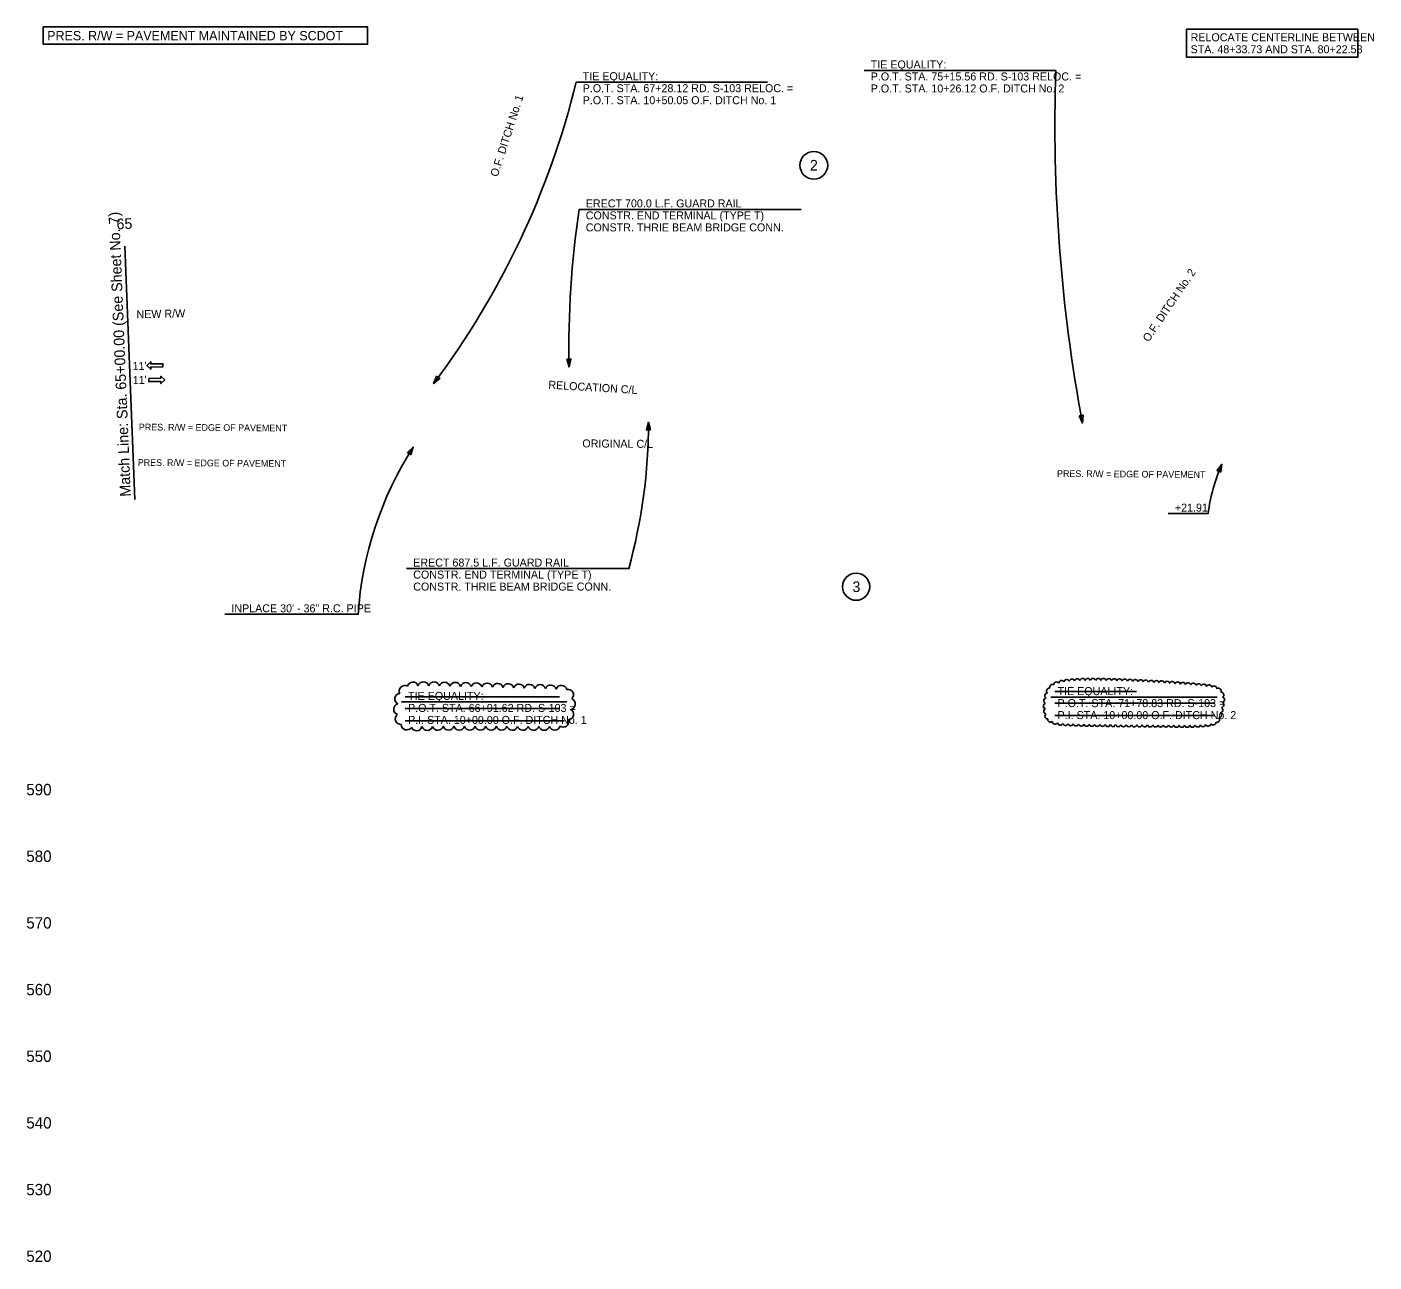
# Model space of a CAD drawing. Extents: x 1964377 to 1966966, y 1116414 to 1123213.
# Drawn here: x 1965294 to 1966305, y 1118827 to 1119753 of the extents above; entities that cross this region are included whole.
import ezdxf

# ---------------------------------------------------------------- set-up
doc = ezdxf.new("R2010")
doc.units = 0
for name, color, linetype in [('RD_DDB_Profile_Elev', 7, 'Continuous'), ('RD_EX_DV_TX_Prop', 7, 'Continuous'), ('RD_EX_RW_TX', 7, 'Continuous'), ('RD_HC_Data', 7, 'Continuous'), ('RD_HC_Data_Rel', 7, 'Continuous'), ('RD_HC_TX_Rel_Sta50', 7, 'Continuous'), ('RD_PD_Final_LnLine', 7, 'Continuous'), ('RD_PD_Final_TX', 7, 'Continuous'), ('RD_PD_RW_TX', 7, 'Continuous'), ('RD_SHT_MatchLine', 7, 'Continuous'), ('RD_TX_Drainage', 7, 'Continuous'), ('RD_TX_Misc1', 7, 'Continuous'), ('RD_TX_RoadID', 7, 'Continuous')]:
    doc.layers.add(name, color=color, linetype=linetype)

msp = doc.modelspace()

# ---------------------------------------------------------------- linework, layer by layer
at = {"layer": 'RD_EX_DV_TX_Prop'}
for centre, radius in [((1965884.4, 1119649.3), 10.4), ((1965916.1, 1119333.2), 10.2)]:
    msp.add_circle(centre, radius, dxfattribs=at)
at = {"layer": 'RD_EX_RW_TX'}
msp.add_lwpolyline([(1965306.5, 1119753), (1965549.8, 1119753), (1965549.8, 1119740), (1965306.5, 1119740)], close=True, dxfattribs=at)
at = {"layer": 'RD_HC_Data'}
for p, q in [((1966065.9, 1119720.4), (1965922.1, 1119720.4)), ((1965849.8, 1119711.6), (1965706.1, 1119711.6)), ((1965578, 1119250.7), (1965693.8, 1119250.7)), ((1966186.9, 1119250.4), (1966062.2, 1119250.4)), ((1966065.2, 1119254.6), (1966126.3, 1119254.6)), ((1965699.2, 1119246.8), (1965575.1, 1119246.8)), ((1965578, 1119241.8), (1965693.8, 1119241.8)), ((1966065.2, 1119245.9), (1966185.2, 1119245.9)), ((1965578, 1119232.6), (1965697.3, 1119232.6)), ((1966065.2, 1119236.7), (1966185.2, 1119236.7))]:
    msp.add_line(p, q, dxfattribs=at)
for points in [[(1965601.5, 1119491.2), (1965599.3, 1119485.6), (1965604, 1119489.3)], [(1966083.3, 1119461.3), (1966085.8, 1119455.9), (1966086.3, 1119461.9)]]:
    msp.add_lwpolyline(points, close=True, dxfattribs=at)
for centre, radius, start, end in [((1967295.8, 1119680.3), 1230.6, 178.134, 190.5081), ((1965098.5, 1119860.4), 625.6, 323.1887, 346.2398), ((1965583.8, 1119257.5), 4.18, 20.7906, 165.7906), ((1965591.6, 1119257.7), 4.18, 16.9558, 161.9558), ((1965599.6, 1119257.6), 4.18, 16.5288, 161.5288), ((1965607.5, 1119257.4), 4.18, 16.3206, 161.3206), ((1965615.5, 1119257.3), 4.18, 16.1908, 161.1908), ((1965623.5, 1119257.1), 4.18, 16.0999, 161.0999), ((1965631.4, 1119256.9), 4.18, 16.0316, 161.0316), ((1965639.4, 1119256.7), 4.18, 15.98, 160.98), ((1965647.3, 1119256.5), 4.18, 15.9578, 160.9578), ((1965655.3, 1119256.3), 4.18, 15.9389, 160.9389), ((1965663.3, 1119256), 4.18, 15.914, 160.914), ((1965671.2, 1119255.8), 4.18, 15.8786, 160.8786), ((1965679.2, 1119255.6), 4.18, 15.8227, 160.8227), ((1966063.3, 1119257.8), 2.08, 56.272, 201.272), ((1966066.5, 1119259.7), 2.08, 38.2854, 183.2854), ((1966070.2, 1119260.8), 2.08, 30.0492, 175.0492), ((1966074.1, 1119261.5), 2.08, 25.3485, 170.3485), ((1966078, 1119261.9), 2.08, 22.2643, 167.2643), ((1966081.9, 1119262.1), 2.08, 20.0771, 165.0771), ((1966085.9, 1119262.3), 2.08, 18.8445, 163.8445), ((1966089.8, 1119262.3), 2.08, 18.0591, 163.0591), ((1966093.8, 1119262.4), 2.08, 17.4369, 162.4369), ((1966097.8, 1119262.3), 2.08, 16.9282, 161.9282), ((1966101.7, 1119262.3), 2.08, 16.5024, 161.5024), ((1966105.7, 1119262.2), 2.08, 16.1392, 161.1392), ((1966109.7, 1119262.1), 2.08, 15.8246, 160.8246), ((1966113.6, 1119262), 2.08, 15.5487, 160.5487), ((1966117.6, 1119261.8), 2.08, 15.3042, 160.3042), ((1966121.5, 1119261.7), 2.08, 15.0855, 160.0855), ((1966125.5, 1119261.5), 2.08, 14.8885, 159.8885), ((1966129.5, 1119261.3), 2.08, 14.7097, 159.7097), ((1966133.4, 1119261.1), 2.08, 14.5465, 159.5465), ((1966137.4, 1119260.9), 2.08, 14.3981, 159.3981), ((1966141.4, 1119260.7), 2.08, 14.2747, 159.2747), ((1966145.3, 1119260.5), 2.08, 14.1444, 159.1444), ((1966149.3, 1119260.2), 2.08, 13.9939, 158.9939), ((1966153.2, 1119260), 2.08, 13.8172, 158.8172), ((1966157.2, 1119259.7), 2.08, 13.6058, 158.6058), ((1966161.2, 1119259.4), 2.08, 13.3464, 158.3464), ((1966165.1, 1119259.1), 2.08, 13.0177, 158.0177), ((1966169.1, 1119258.8), 2.08, 12.582, 157.582), ((1966173, 1119258.4), 2.08, 11.9646, 156.9646), ((1966176.9, 1119258), 2.08, 10.9876, 155.9876), ((1966180.9, 1119257.5), 2.08, 9.0547, 154.0547), ((1965574.4, 1119249), 4.18, 96.8101, 241.8101), ((1965577.6, 1119254.9), 4.18, 60.4349, 205.4349), ((1965687.1, 1119255.3), 4.18, 15.7119, 160.7119), ((1965695.1, 1119255), 4.18, 14.634, 159.634), ((1965700, 1119252), 4.17, 316.7444, 101.7444), ((1966058.9, 1119247.6), 2.08, 101.143, 246.143), ((1966059.7, 1119251.4), 2.08, 92.1655, 237.1655), ((1966061, 1119255), 2.08, 81.1827, 226.1827), ((1966184.6, 1119256.7), 2.08, 0.9605, 145.9605), ((1966187.8, 1119255), 2.08, 337.4399, 122.4399), ((1966189.8, 1119252.1), 2.08, 306.1235, 91.1235), ((1966190.3, 1119248.4), 2.08, 284.5038, 69.5038), ((1965573.5, 1119241.3), 4.18, 105.3418, 250.3418), ((1965700, 1119237.6), 4.18, 275.0474, 60.0474), ((1965701.3, 1119245.3), 4.18, 281.2192, 66.2192), ((1966058.7, 1119243.7), 2.08, 108.0766, 253.0766), ((1966058.9, 1119239.8), 2.08, 112.7273, 257.7273), ((1966189.1, 1119240.7), 2.08, 275.3079, 60.3079), ((1966189.8, 1119244.6), 2.08, 276.9168, 61.9168), ((1965574.7, 1119234.1), 4.18, 128.6223, 273.6223), ((1965579.1, 1119230), 4.18, 181.8868, 326.8868), ((1965696.5, 1119232), 4.17, 235.1987, 20.1987), ((1966059.8, 1119236.2), 2.08, 127.7004, 272.7004), ((1966061.9, 1119233.7), 2.08, 168.5015, 313.5015), ((1966065.4, 1119232.2), 2.08, 181.934, 326.934), ((1966069.2, 1119231.5), 2.08, 191.995, 336.995), ((1966073.1, 1119231.2), 2.08, 194.108, 339.108), ((1966077.1, 1119231), 2.08, 195.0541, 340.0541), ((1966081, 1119230.9), 2.08, 195.6246, 340.6246), ((1966085, 1119230.7), 2.08, 196.0169, 341.0169), ((1966089, 1119230.6), 2.08, 196.308, 341.308), ((1966092.9, 1119230.6), 2.08, 196.5352, 341.5352), ((1966096.9, 1119230.5), 2.08, 196.7189, 341.7189), ((1966100.9, 1119230.5), 2.08, 196.8711, 341.8711), ((1966104.8, 1119230.4), 2.08, 196.9319, 341.9319), ((1966108.8, 1119230.4), 2.08, 196.9343, 341.9343), ((1966112.8, 1119230.3), 2.08, 196.9368, 341.9368), ((1966116.7, 1119230.3), 2.08, 196.9395, 341.9395), ((1966120.7, 1119230.3), 2.08, 196.9423, 341.9423), ((1966124.7, 1119230.2), 2.08, 196.9453, 341.9453), ((1966128.7, 1119230.2), 2.08, 196.9484, 341.9484), ((1966132.6, 1119230.2), 2.08, 196.9517, 341.9517), ((1966136.6, 1119230.1), 2.08, 196.9553, 341.9553), ((1966140.6, 1119230.1), 2.08, 196.959, 341.959), ((1966144.5, 1119230), 2.08, 196.9631, 341.9631), ((1966148.5, 1119230), 2.08, 196.9674, 341.9674), ((1966152.5, 1119230), 2.08, 196.972, 341.972), ((1966156.4, 1119229.9), 2.08, 196.9771, 341.9771), ((1966160.4, 1119229.9), 2.08, 197.0169, 342.0169), ((1966164.4, 1119229.9), 2.08, 197.636, 342.636), ((1966168.3, 1119229.9), 2.08, 198.652, 343.652), ((1966172.3, 1119230.1), 2.08, 200.0417, 345.0417), ((1966176.2, 1119230.3), 2.08, 202.1073, 347.1073), ((1966180.1, 1119230.7), 2.08, 205.6578, 350.6578), ((1966183.9, 1119231.6), 2.08, 214.1692, 359.1692), ((1966186.6, 1119233.5), 2.08, 253.1735, 38.1735), ((1966188.1, 1119236.9), 2.08, 272.443, 57.443), ((1965586.5, 1119229.3), 4.18, 201.258, 346.258), ((1965594.5, 1119229.6), 4.18, 198.7023, 343.7023), ((1965602.5, 1119229.7), 4.18, 197.8861, 342.8861), ((1965610.5, 1119229.8), 4.18, 197.6341, 342.6341), ((1965618.5, 1119229.8), 4.18, 197.5505, 342.5505), ((1965626.4, 1119229.8), 4.18, 197.4898, 342.4898), ((1965634.4, 1119229.8), 4.18, 197.4431, 342.4431), ((1965642.4, 1119229.8), 4.18, 197.4057, 342.4057), ((1965650.3, 1119229.8), 4.18, 197.3782, 342.3782), ((1965658.3, 1119229.7), 4.18, 197.3797, 342.3797), ((1965666.2, 1119229.7), 4.18, 197.3893, 342.3893), ((1965674.2, 1119229.7), 4.18, 197.4041, 342.4041), ((1965682.2, 1119229.7), 4.18, 197.4325, 342.4325), ((1965690.1, 1119229.8), 4.18, 198.4724, 343.4724)]:
    msp.add_arc(centre, radius, start, end, dxfattribs=at)
at = {"layer": 'RD_HC_Data_Rel'}
msp.add_lwpolyline([(1966164, 1119751.3), (1966292.3, 1119751.3), (1966292.3, 1119730.3), (1966164, 1119730.3)], close=True, dxfattribs=at)
at = {"layer": 'RD_PD_Final_LnLine'}
for points in [[(1965396.3, 1119498), (1965396.3, 1119500.4), (1965387.1, 1119500.3), (1965387.1, 1119501.9), (1965384.3, 1119499.1), (1965387.2, 1119496.3), (1965387.1, 1119497.9)], [(1965385.6, 1119489.4), (1965385.6, 1119487), (1965394.8, 1119487.1), (1965394.8, 1119485.5), (1965397.6, 1119488.3), (1965394.7, 1119491.1), (1965394.7, 1119489.5)]]:
    msp.add_lwpolyline(points, close=True, dxfattribs=at)
at = {"layer": 'RD_PD_RW_TX'}
msp.add_line((1966180.1, 1119388), (1966150.2, 1119388), dxfattribs=at)
msp.add_lwpolyline([(1966189.6, 1119419.2), (1966190.5, 1119425.1), (1966186.8, 1119420.4)], close=True, dxfattribs=at)
msp.add_arc((1966317.9, 1119369.3), 139.1, 156.3482, 172.28, dxfattribs=at)
at = {"layer": 'RD_SHT_MatchLine'}
msp.add_lwpolyline([(1965375.3, 1119398.6), (1965371.4, 1119493.5), (1965367.6, 1119588.5)], dxfattribs=at)
at = {"layer": 'RD_TX_Drainage'}
msp.add_line((1965542.7, 1119312.5), (1965442.6, 1119312.5), dxfattribs=at)
msp.add_lwpolyline([(1965582.2, 1119432.2), (1965584, 1119437.9), (1965579.6, 1119433.9)], close=True, dxfattribs=at)
msp.add_arc((1965806.7, 1119295), 264.6, 147.3047, 176.2141, dxfattribs=at)
at = {"layer": 'RD_TX_Misc1'}
for p, q in [((1965875, 1119616.2), (1965708.4, 1119616.2)), ((1965745.6, 1119346.8), (1965579, 1119346.8))]:
    msp.add_line(p, q, dxfattribs=at)
for points in [[(1965699.2, 1119503.8), (1965700.9, 1119498.1), (1965702.3, 1119503.9)], [(1965762, 1119450.8), (1965760.5, 1119456.6), (1965758.9, 1119450.8)]]:
    msp.add_lwpolyline(points, close=True, dxfattribs=at)
for centre, radius, start, end in [((1966432.9, 1119510.5), 732.2, 171.7025, 180.9735), ((1965342.8, 1119457.4), 417.7, 344.6325, 359.8853)]:
    msp.add_arc(centre, radius, start, end, dxfattribs=at)

# ---------------------------------------------------------------- texts
at = {"layer": 'RD_DDB_Profile_Elev'}
for s, p in [('590', (1965293.8, 1119176.8)), ('580', (1965293.8, 1119126.8)), ('570', (1965293.8, 1119076.8)), ('560', (1965293.8, 1119026.8)), ('550', (1965293.8, 1118976.8)), ('540', (1965293.8, 1118926.8)), ('530', (1965293.8, 1118876.8)), ('520', (1965293.8, 1118826.8))]:
    msp.add_text(s, height=8.5, dxfattribs=at).set_placement(p)
at = {"layer": 'RD_EX_DV_TX_Prop'}
for s, p in [('2', (1965881.5, 1119645.3)), ('3', (1965913.4, 1119329.2))]:
    msp.add_text(s, height=8, dxfattribs=at).set_placement(p)
at = {"layer": 'RD_EX_RW_TX'}
msp.add_text('PRES. R/W = PAVEMENT MAINTAINED BY SCDOT', height=7, dxfattribs=at).set_placement((1965309.5, 1119743))
for p in [(1965378.2, 1119450.5), (1965377.4, 1119423.9), (1966066.8, 1119415.6)]:
    msp.add_text('PRES. R/W = EDGE OF PAVEMENT', height=5, rotation=359.5679, dxfattribs=at).set_placement(p)
at = {"layer": 'RD_HC_Data'}
for s, p in [('TIE EQUALITY:', (1965927.1, 1119721.9)), ('TIE EQUALITY:', (1965711.1, 1119713.1)), ('P.O.T. STA. 75+15.56 RD. S-103 RELOC. =', (1965927.1, 1119712.9)), ('P.O.T. STA. 67+28.12 RD. S-103 RELOC. =', (1965711.1, 1119704.1)), ('P.O.T. STA. 10+26.12 O.F. DITCH No. 2', (1965927.1, 1119703.9)), ('P.O.T. STA. 10+50.05 O.F. DITCH No. 1', (1965711.1, 1119695.1)), ('TIE EQUALITY:', (1965580.1, 1119248.3)), ('TIE EQUALITY:', (1966067.2, 1119251.9)), ('P.O.T. STA. 66+91.62 RD. S-103 =', (1965580.1, 1119239.3)), ('P.O.T. STA. 71+78.83 RD. S-103 =', (1966067.2, 1119242.9)), ('P.I. STA. 10+00.00 O.F. DITCH No. 2', (1966067.2, 1119233.9)), ('P.I. STA. 10+00.00 O.F. DITCH No. 1', (1965580.1, 1119230.3))]:
    msp.add_text(s, height=6, dxfattribs=at).set_placement(p)
at = {"layer": 'RD_HC_Data_Rel'}
for s, p in [('RELOCATE CENTERLINE BETWEEN', (1966167, 1119742.3)), ('STA. 48+33.73 AND STA. 80+22.58', (1966167, 1119733.3))]:
    msp.add_text(s, height=6, dxfattribs=at).set_placement(p)
msp.add_text('RELOCATION C/L', height=6, rotation=356.5074, dxfattribs=at).set_placement((1965685.2, 1119481.8))
at = {"layer": 'RD_HC_TX_Rel_Sta50'}
msp.add_text('65', height=8, rotation=2.3486, dxfattribs=at).set_placement((1965361.6, 1119601.2))
at = {"layer": 'RD_PD_Final_TX'}
for p in [(1965373.6, 1119495.6), (1965373.7, 1119485.1)]:
    msp.add_text("11'", height=6, rotation=1.7022, dxfattribs=at).set_placement(p)
at = {"layer": 'RD_PD_RW_TX'}
msp.add_text('NEW R/W', height=6, rotation=1.1989, dxfattribs=at).set_placement((1965376.5, 1119534.5))
msp.add_text('+21.91', height=6, dxfattribs=at).set_placement((1966155.2, 1119389.5))
at = {"layer": 'RD_SHT_MatchLine'}
msp.add_text('Match Line: Sta. 65+00.00 (See Sheet No. 7)', height=8, rotation=92.3486, dxfattribs=at).set_placement((1965372.2, 1119400.9))
at = {"layer": 'RD_TX_Drainage'}
msp.add_text('INPLACE 30\' - 36" R.C. PIPE', height=6, dxfattribs=at).set_placement((1965447.6, 1119314))
at = {"layer": 'RD_TX_Misc1'}
for s, p in [('ERECT 700.0 L.F. GUARD RAIL', (1965713.4, 1119617.7)), ('CONSTR. END TERMINAL (TYPE T)', (1965713.4, 1119608.7)), ('CONSTR. THRIE BEAM BRIDGE CONN.', (1965713.4, 1119599.7)), ('ERECT 687.5 L.F. GUARD RAIL', (1965584, 1119348.3)), ('CONSTR. END TERMINAL (TYPE T)', (1965584, 1119339.3)), ('CONSTR. THRIE BEAM BRIDGE CONN.', (1965584, 1119330.3))]:
    msp.add_text(s, height=6, dxfattribs=at).set_placement(p)
at = {"layer": 'RD_TX_RoadID'}
for s, rotation, p in [('O.F. DITCH No. 1', 72.2111, (1965647.3, 1119640.2)), ('O.F. DITCH No. 2', 55.9186, (1966135.5, 1119516.3)), ('ORIGINAL C/L', 359.5679, (1965710.8, 1119437.7))]:
    msp.add_text(s, height=6, rotation=rotation, dxfattribs=at).set_placement(p)

doc.saveas('drawing.dxf')
